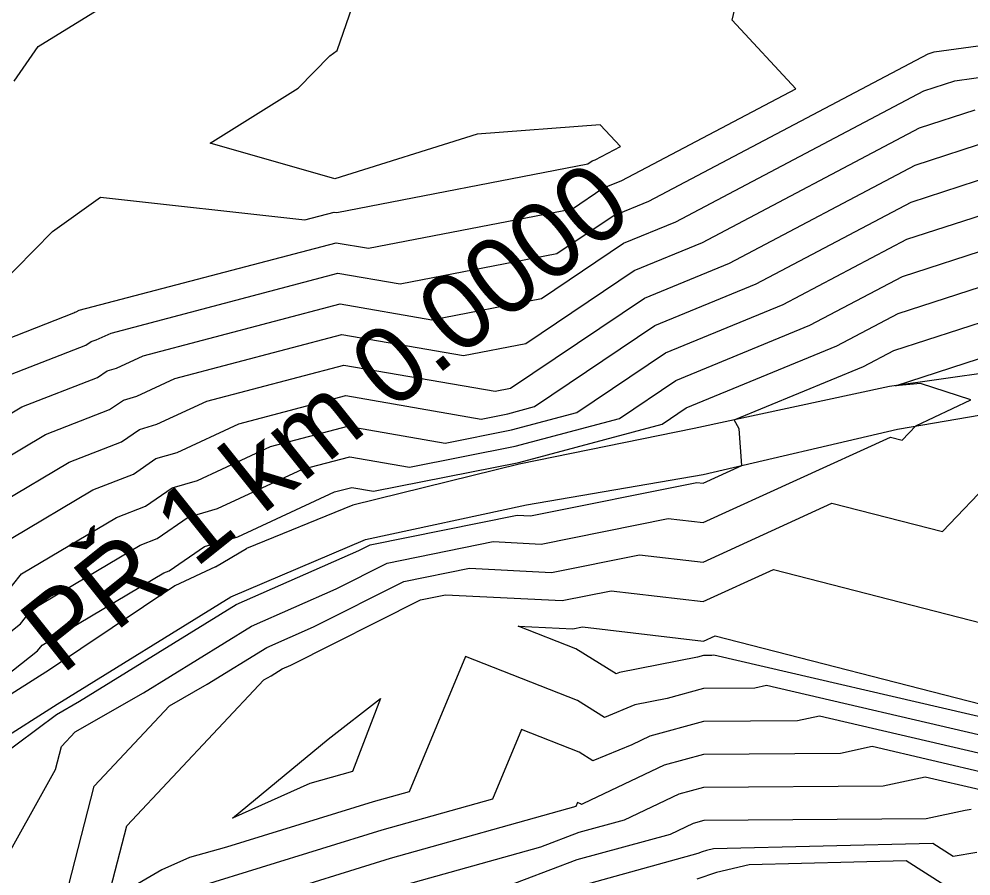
# Model space of a CAD drawing. Extents: x -549238 to -546764, y -1036895 to -1033794.
# Drawn here: x -548075.3 to -547962.9, y -1035605.4 to -1035504.2 of the extents above; entities that cross this region are included whole.
import ezdxf

# ---------------------------------------------------------------- set-up
doc = ezdxf.new("R2010")
doc.units = 0
for name, color, linetype in [('hlavni_vrst', 7, 'Continuous'), ('hrana_L', 7, 'Continuous'), ('norm_vrst', 7, 'Continuous'), ('x_popis_pricne_rezy_C12', 7, 'Continuous')]:
    doc.layers.add(name, color=color, linetype=linetype)

msp = doc.modelspace()

# ---------------------------------------------------------------- linework, layer by layer
at = {"layer": 'hlavni_vrst'}
for p, q in [((-548037.74, -1035507.93), (-548023.71, -1035467.04)), ((-548038.63, -1035508.58), (-548037.74, -1035507.93)), ((-548042.35, -1035512.4), (-548038.63, -1035508.58)), ((-548052.76, -1035518.87), (-548042.35, -1035512.4)), ((-548006.66, -1035516.7), (-548021.22, -1035517.83)), ((-548004.28, -1035519.26), (-548006.66, -1035516.7)), ((-548021.22, -1035517.83), (-548038.03, -1035523.08)), ((-547969.44, -1035521.47), (-547959.92, -1035518.38)), ((-548038.03, -1035523.08), (-548052.76, -1035518.87)), ((-548007.27, -1035520.84), (-548004.28, -1035519.26)), ((-548037.79, -1035527.08), (-548008.12, -1035521.32)), ((-548008.12, -1035521.32), (-548007.6, -1035520.97)), ((-548007.6, -1035520.97), (-548007.27, -1035520.84)), ((-547991.41, -1035533.05), (-547969.44, -1035521.47)), ((-548071.37, -1035529.32), (-548065.71, -1035525.26)), ((-548065.71, -1035525.26), (-548041.55, -1035527.93)), ((-548041.55, -1035527.93), (-548038.11, -1035527.03)), ((-548038.11, -1035527.03), (-548037.79, -1035527.08)), ((-548081.43, -1035539.48), (-548071.37, -1035529.32)), ((-548001.44, -1035537.19), (-547991.41, -1035533.05)), ((-547971.98, -1035543.39), (-547947.79, -1035535.53)), ((-548017.27, -1035547.84), (-548001.44, -1035537.19)), ((-547975.55, -1035545.27), (-547971.98, -1035543.39)), ((-548053.15, -1035549.36), (-548036.95, -1035545.09)), ((-548036.95, -1035545.09), (-548019.06, -1035548.19)), ((-547990.84, -1035551.58), (-547975.55, -1035545.27)), ((-548019.06, -1035548.19), (-548017.27, -1035547.84)), ((-548059.04, -1035552.09), (-548053.15, -1035549.36)), ((-548061.09, -1035552.69), (-548059.04, -1035552.09)), ((-547990.26, -1035552.61), (-547990.84, -1035551.58)), ((-548063.23, -1035554.17), (-548061.09, -1035552.69)), ((-547989.92, -1035556.95), (-547990.26, -1035552.61)), ((-548069.41, -1035556.58), (-548063.23, -1035554.17)), ((-548077.48, -1035561.37), (-548069.41, -1035556.58)), ((-547994.52, -1035559.05), (-547989.92, -1035556.95)), ((-548014.9, -1035562.89), (-547995.26, -1035558.96)), ((-547995.26, -1035558.96), (-547994.52, -1035559.05)), ((-548033.83, -1035566.34), (-548016.49, -1035562.81)), ((-548016.49, -1035562.81), (-548014.9, -1035562.89)), ((-548035.18, -1035567.02), (-548033.83, -1035566.34)), ((-548049.67, -1035573.38), (-548035.18, -1035567.02)), ((-548068.19, -1035584.8), (-548049.67, -1035573.38)), ((-548070.93, -1035586.38), (-548068.19, -1035584.8)), ((-548082.34, -1035594.86), (-548070.93, -1035586.38)), ((-547968.29, -1035593.77), (-547973.23, -1035594.84)), ((-547961.77, -1035595.29), (-547968.29, -1035593.77)), ((-547994.45, -1035595.01), (-547997.39, -1035595.8)), ((-547973.23, -1035594.84), (-547994.45, -1035595.01)), ((-547997.39, -1035595.8), (-548003.85, -1035598.87)), ((-548003.85, -1035598.87), (-548009.18, -1035600.33)), ((-548009.18, -1035600.33), (-548013.71, -1035602.03)), ((-548013.71, -1035602.03), (-548030.5, -1035606.72))]:
    msp.add_line(p, q, dxfattribs=at)
at = {"layer": 'hrana_L'}
for p, q in [((-547942.25, -1035543.35), (-547972.47, -1035547.64)), ((-547972.47, -1035547.64), (-547995.58, -1035552.59)), ((-547971.54, -1035552.66), (-547942.64, -1035547.74)), ((-547995.58, -1035552.59), (-548016.23, -1035556.8)), ((-547994.52, -1035558.02), (-547971.54, -1035552.66)), ((-548016.23, -1035556.8), (-548035.89, -1035561.64)), ((-548015.39, -1035561.59), (-547994.52, -1035558.02)), ((-548035.89, -1035561.64), (-548048.48, -1035566.77)), ((-548034.4, -1035565.71), (-548015.39, -1035561.59)), ((-548050.32, -1035572.47), (-548034.4, -1035565.71)), ((-548052.12, -1035568.92), (-548048.48, -1035566.77)), ((-548052.12, -1035568.92), (-548056.93, -1035571.19)), ((-548056.93, -1035571.19), (-548071.74, -1035581.11)), ((-548070.83, -1035585.15), (-548050.32, -1035572.47)), ((-548071.74, -1035581.11), (-548104.41, -1035601.7)), ((-548102.26, -1035605.09), (-548070.83, -1035585.15))]:
    msp.add_line(p, q, dxfattribs=at)
at = {"layer": 'norm_vrst'}
for p, q in [((-547991.06, -1035504.34), (-547990.11, -1035500.23)), ((-548073.07, -1035507.45), (-548064.07, -1035501.86)), ((-547983.55, -1035512.45), (-547991.06, -1035504.34)), ((-547967.21, -1035508.09), (-547941.64, -1035504.6)), ((-548075.93, -1035511.56), (-548073.07, -1035507.45)), ((-548000.93, -1035525.72), (-547967.91, -1035508.32)), ((-547967.91, -1035508.32), (-547967.21, -1035508.09)), ((-547964.78, -1035511.52), (-547941.7, -1035508.37)), ((-547968.42, -1035512.71), (-547964.78, -1035511.52)), ((-548004.1, -1035523.28), (-547983.55, -1035512.45)), ((-547997.75, -1035528.17), (-547968.42, -1035512.71)), ((-547968.93, -1035517.09), (-547962.35, -1035514.95)), ((-547994.58, -1035530.61), (-547968.93, -1035517.09)), ((-547969.94, -1035525.86), (-547957.5, -1035521.81)), ((-548006.37, -1035524.21), (-548004.1, -1035523.28)), ((-548009.95, -1035526.63), (-548006.37, -1035524.21)), ((-547970.45, -1035530.24), (-547955.07, -1035525.24)), ((-548005.13, -1035527.46), (-548000.93, -1035525.72)), ((-547988.24, -1035535.5), (-547969.94, -1035525.86)), ((-548034.05, -1035531.3), (-548009.95, -1035526.63)), ((-548011.78, -1035531.93), (-548005.13, -1035527.46)), ((-548003.9, -1035530.7), (-547997.75, -1035528.17)), ((-547970.96, -1035534.62), (-547952.64, -1035528.67)), ((-548068.23, -1035538.63), (-548037.88, -1035530.64)), ((-548037.88, -1035530.64), (-548034.05, -1035531.3)), ((-548013.61, -1035537.23), (-548003.9, -1035530.7)), ((-548002.67, -1035533.94), (-547994.58, -1035530.61)), ((-547985.06, -1035537.94), (-547970.45, -1035530.24)), ((-548030.3, -1035535.52), (-548011.78, -1035531.93)), ((-547971.47, -1035539), (-547950.21, -1035532.1)), ((-548064.46, -1035541.32), (-548037.65, -1035534.25)), ((-548037.65, -1035534.25), (-548030.3, -1035535.52)), ((-548015.44, -1035542.54), (-548002.67, -1035533.94)), ((-547981.89, -1035540.38), (-547970.96, -1035534.62)), ((-548000.2, -1035540.43), (-547988.24, -1035535.5)), ((-548026.55, -1035539.75), (-548013.61, -1035537.23)), ((-548068.6, -1035538.81), (-548068.23, -1035538.63)), ((-548060.69, -1035544), (-548037.41, -1035537.86)), ((-548037.41, -1035537.86), (-548026.55, -1035539.75)), ((-547998.97, -1035543.67), (-547985.06, -1035537.94)), ((-548080.58, -1035543.51), (-548068.87, -1035538.94)), ((-548068.87, -1035538.94), (-548068.73, -1035538.84)), ((-548068.73, -1035538.84), (-548068.6, -1035538.81)), ((-547978.72, -1035542.83), (-547971.47, -1035539)), ((-547971.78, -1035547.54), (-547945.36, -1035538.96)), ((-548014.44, -1035550.01), (-548000.2, -1035540.43)), ((-547997.74, -1035546.91), (-547981.89, -1035540.38)), ((-548066.82, -1035542.31), (-548066.21, -1035542.13)), ((-548066.21, -1035542.13), (-548064.46, -1035541.32)), ((-548056.92, -1035546.68), (-548037.18, -1035541.48)), ((-548037.18, -1035541.48), (-548022.81, -1035543.97)), ((-548077.79, -1035546.77), (-548067.46, -1035542.75)), ((-548067.46, -1035542.75), (-548066.82, -1035542.31)), ((-548022.81, -1035543.97), (-548015.44, -1035542.54)), ((-547996.5, -1035550.16), (-547978.72, -1035542.83)), ((-548063.82, -1035545.45), (-548060.69, -1035544)), ((-548009.41, -1035550.7), (-547998.97, -1035543.67)), ((-548064.91, -1035545.77), (-548063.82, -1035545.45)), ((-548074.99, -1035550.04), (-548066.05, -1035546.55)), ((-548066.05, -1035546.55), (-548064.91, -1035545.77)), ((-548061.43, -1035548.77), (-548056.92, -1035546.68)), ((-548004.38, -1035551.39), (-547997.74, -1035546.91)), ((-547968.82, -1035547.26), (-547971.78, -1035547.54)), ((-547962.89, -1035549.19), (-547968.82, -1035547.26)), ((-548063, -1035549.23), (-548061.43, -1035548.77)), ((-548049.38, -1035552.04), (-548036.72, -1035548.7)), ((-548036.72, -1035548.7), (-548020.74, -1035551.47)), ((-548079.92, -1035552.97), (-548074.99, -1035550.04)), ((-548064.64, -1035550.36), (-548063, -1035549.23)), ((-548017.57, -1035550.84), (-548014.44, -1035550.01)), ((-547969.39, -1035552.29), (-547962.89, -1035549.19)), ((-547966.24, -1035564.77), (-547951.44, -1035549.24)), ((-548072.2, -1035553.31), (-548064.64, -1035550.36)), ((-548020.74, -1035551.47), (-548017.57, -1035550.84)), ((-548017.14, -1035552.76), (-548009.41, -1035550.7)), ((-547999.35, -1035552.07), (-547996.5, -1035550.16)), ((-548056.65, -1035555.41), (-548049.38, -1035552.04)), ((-548016.71, -1035554.67), (-548004.38, -1035551.39)), ((-548016.28, -1035556.59), (-547999.35, -1035552.07)), ((-547970.97, -1035553.96), (-547969.39, -1035552.29)), ((-548078.7, -1035557.17), (-548072.2, -1035553.31)), ((-548045.62, -1035554.72), (-548036.49, -1035552.32)), ((-548036.49, -1035552.32), (-548024.97, -1035554.31)), ((-548024.97, -1035554.31), (-548017.14, -1035552.76)), ((-547994.51, -1035563.71), (-547972.37, -1035553.6)), ((-547972.37, -1035553.6), (-547970.97, -1035553.96)), ((-548059.17, -1035556.15), (-548056.65, -1035555.41)), ((-548054.26, -1035558.73), (-548045.62, -1035554.72)), ((-548029.2, -1035557.15), (-548016.71, -1035554.67)), ((-548061.82, -1035557.98), (-548059.17, -1035556.15)), ((-548041.85, -1035557.4), (-548036.26, -1035555.93)), ((-548036.26, -1035555.93), (-548029.2, -1035557.15)), ((-548033.44, -1035559.99), (-548016.28, -1035556.59)), ((-548051.87, -1035562.05), (-548041.85, -1035557.4)), ((-548066.62, -1035559.85), (-548061.82, -1035557.98)), ((-548057.26, -1035559.61), (-548054.26, -1035558.73)), ((-548076.26, -1035565.57), (-548066.62, -1035559.85)), ((-548060.41, -1035561.78), (-548057.26, -1035559.61)), ((-548049.48, -1035565.38), (-548038.08, -1035560.08)), ((-548038.08, -1035560.08), (-548036.02, -1035559.54)), ((-548036.02, -1035559.54), (-548033.44, -1035559.99)), ((-548063.83, -1035563.12), (-548060.41, -1035561.78)), ((-548055.35, -1035563.07), (-548051.87, -1035562.05)), ((-547994.5, -1035568.38), (-547979.28, -1035561.42)), ((-547979.28, -1035561.42), (-547966.24, -1035564.77)), ((-548075.04, -1035569.77), (-548063.83, -1035563.12)), ((-548059, -1035565.59), (-548055.35, -1035563.07)), ((-548013.66, -1035566.24), (-547998.64, -1035563.23)), ((-547998.64, -1035563.23), (-547994.51, -1035563.71)), ((-548061.03, -1035566.39), (-548059, -1035565.59)), ((-548053.44, -1035566.53), (-548049.48, -1035565.38)), ((-548073.82, -1035573.97), (-548061.03, -1035566.39)), ((-548057.59, -1035569.4), (-548053.44, -1035566.53)), ((-548031.85, -1035568.5), (-548019.3, -1035565.95)), ((-548019.3, -1035565.95), (-548013.66, -1035566.24)), ((-548012.41, -1035569.58), (-548002.01, -1035567.5)), ((-548002.01, -1035567.5), (-547994.5, -1035568.38)), ((-548037.86, -1035571.52), (-548031.85, -1035568.5)), ((-548029.87, -1035570.66), (-548022.11, -1035569.09)), ((-548022.11, -1035569.09), (-548012.41, -1035569.58)), ((-548077.17, -1035572.45), (-548075.04, -1035569.77)), ((-548072.6, -1035578.17), (-548058.24, -1035569.65)), ((-548058.24, -1035569.65), (-548057.59, -1035569.4)), ((-547994.49, -1035573.04), (-547986.19, -1035569.25)), ((-547986.19, -1035569.25), (-547961.52, -1035575.59)), ((-548040.53, -1035576.03), (-548029.87, -1035570.66)), ((-548047.86, -1035575.92), (-548037.86, -1035571.52)), ((-548027.9, -1035572.83), (-548024.93, -1035572.22)), ((-548024.93, -1035572.22), (-548011.16, -1035572.92)), ((-548011.16, -1035572.92), (-548005.38, -1035571.76)), ((-548005.38, -1035571.76), (-547994.49, -1035573.04)), ((-548043.21, -1035580.53), (-548027.9, -1035572.83)), ((-548075.16, -1035575.66), (-548073.82, -1035573.97)), ((-548103.67, -1035598.15), (-548075.16, -1035575.66)), ((-548060.65, -1035583.8), (-548047.86, -1035575.92)), ((-548046.05, -1035578.45), (-548040.53, -1035576.03)), ((-548016.37, -1035575.94), (-548009.91, -1035576.26)), ((-548009.55, -1035578.63), (-548016.37, -1035575.94)), ((-548009.91, -1035576.26), (-548008.76, -1035576.03)), ((-548008.76, -1035576.03), (-547994.48, -1035577.71)), ((-547994.48, -1035577.71), (-547993.1, -1035577.07)), ((-547993.1, -1035577.07), (-547956.79, -1035586.4)), ((-548092.92, -1035594.46), (-548073.15, -1035578.86)), ((-548073.15, -1035578.86), (-548072.6, -1035578.17)), ((-548053.11, -1035582.8), (-548046.05, -1035578.45)), ((-548004.8, -1035581.58), (-548009.55, -1035578.63)), ((-548022.58, -1035579.52), (-548029.24, -1035595.49)), ((-548009.36, -1035584.73), (-548022.58, -1035579.52)), ((-547995.19, -1035579.61), (-548004.39, -1035581.41)), ((-547994.48, -1035579.42), (-547995.19, -1035579.61)), ((-547993.47, -1035579.41), (-547994.48, -1035579.42)), ((-547993.23, -1035579.36), (-547993.47, -1035579.41)), ((-547956.38, -1035587.92), (-547993.23, -1035579.36)), ((-548045.56, -1035581.8), (-548044.25, -1035580.99)), ((-548044.25, -1035580.99), (-548043.21, -1035580.53)), ((-548004.39, -1035581.41), (-548004.8, -1035581.58)), ((-548062.6, -1035599.51), (-548046.4, -1035582.28)), ((-548046.4, -1035582.28), (-548045.56, -1035581.8)), ((-548057.55, -1035585.36), (-548053.11, -1035582.8)), ((-547994.47, -1035583.32), (-547998.76, -1035584.48)), ((-547988.41, -1035583.27), (-547994.47, -1035583.32)), ((-547987, -1035582.96), (-547988.41, -1035583.27)), ((-547957.73, -1035589.76), (-547987, -1035582.96)), ((-548068.71, -1035588.44), (-548060.65, -1035583.8)), ((-548038.82, -1035589.27), (-548032.62, -1035584.48)), ((-548032.62, -1035584.48), (-548035.94, -1035593.12)), ((-548006.16, -1035586.72), (-548009.36, -1035584.73)), ((-547998.76, -1035584.48), (-548002.58, -1035585.22)), ((-548066.45, -1035594.83), (-548057.55, -1035585.36)), ((-548002.58, -1035585.22), (-548006.16, -1035586.72)), ((-547983.35, -1035587.13), (-547994.47, -1035587.21)), ((-547980.76, -1035586.57), (-547983.35, -1035587.13)), ((-547959.08, -1035591.6), (-547980.76, -1035586.57)), ((-548015.97, -1035588.15), (-548019.4, -1035596.37)), ((-548009.17, -1035590.83), (-548015.97, -1035588.15)), ((-547994.47, -1035587.21), (-548000.81, -1035588.93)), ((-548070.31, -1035590.15), (-548068.71, -1035588.44)), ((-548050.13, -1035598.6), (-548038.82, -1035589.27)), ((-548000.81, -1035588.93), (-548002.95, -1035589.94)), ((-548071.02, -1035592.88), (-548070.31, -1035590.15)), ((-548002.95, -1035589.94), (-548007.52, -1035591.85)), ((-547974.53, -1035590.17), (-547978.29, -1035590.98)), ((-547960.42, -1035593.45), (-547974.53, -1035590.17)), ((-548007.52, -1035591.85), (-548009.17, -1035590.83)), ((-547994.46, -1035591.11), (-547999.1, -1035592.36)), ((-547978.29, -1035590.98), (-547994.46, -1035591.11)), ((-547999.1, -1035592.36), (-548008.63, -1035596.88)), ((-548081.01, -1035610.73), (-548071.02, -1035592.88)), ((-548035.94, -1035593.12), (-548040.98, -1035594.52)), ((-548070.38, -1035610), (-548066.45, -1035594.83)), ((-548040.98, -1035594.52), (-548050.13, -1035598.6)), ((-548029.24, -1035595.49), (-548033.48, -1035596.68)), ((-548033.48, -1035596.68), (-548050.81, -1035602.06)), ((-548019.4, -1035596.37), (-548032.49, -1035600.03)), ((-548009.56, -1035597.25), (-548031.5, -1035603.37)), ((-548009.37, -1035596.78), (-548009.56, -1035597.25)), ((-548008.98, -1035596.93), (-548009.37, -1035596.78)), ((-548008.89, -1035596.99), (-548008.98, -1035596.93)), ((-548008.63, -1035596.88), (-548008.89, -1035596.99)), ((-547963.56, -1035597.7), (-547968.17, -1035598.7)), ((-547962.83, -1035597.59), (-547963.56, -1035597.7)), ((-548064.91, -1035608.46), (-548062.6, -1035599.51)), ((-547995.69, -1035599.24), (-547998.41, -1035600.53)), ((-547994.44, -1035598.91), (-547995.69, -1035599.24)), ((-547968.17, -1035598.7), (-547994.44, -1035598.91)), ((-548032.49, -1035600.03), (-548053.86, -1035606.67)), ((-547998.41, -1035600.53), (-548009.41, -1035603.56)), ((-547967.38, -1035601.61), (-547993.3, -1035602.25)), ((-547964.97, -1035603.14), (-547967.38, -1035601.61)), ((-548050.81, -1035602.06), (-548055.19, -1035603.28)), ((-547995.14, -1035602.8), (-548009.64, -1035606.79)), ((-547994.61, -1035602.61), (-547995.14, -1035602.8)), ((-547994.12, -1035602.45), (-547994.61, -1035602.61)), ((-547993.3, -1035602.25), (-547994.12, -1035602.45)), ((-547962.15, -1035602.69), (-547964.97, -1035603.14)), ((-548055.19, -1035603.28), (-548058.46, -1035604.73)), ((-548031.5, -1035603.37), (-548048.4, -1035608.63)), ((-548009.41, -1035603.56), (-548018.76, -1035607.07)), ((-547970.53, -1035603.66), (-547989.07, -1035604.12)), ((-547963.48, -1035608.12), (-547970.53, -1035603.66)), ((-548058.46, -1035604.73), (-548064.91, -1035608.46)), ((-547992.93, -1035605.03), (-547995.26, -1035605.81)), ((-547989.07, -1035604.12), (-547992.93, -1035605.03))]:
    msp.add_line(p, q, dxfattribs=at)

# ---------------------------------------------------------------- texts
at = {"layer": 'x_popis_pricne_rezy_C12'}
msp.add_text('PŘ 1 km 0.0000', height=9.0627, rotation=38.6103, dxfattribs=at).set_placement((-548070.31, -1035581.78))

doc.saveas('drawing.dxf')
